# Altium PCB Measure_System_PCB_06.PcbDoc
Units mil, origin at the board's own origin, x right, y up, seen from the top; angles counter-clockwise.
Board outline 5905.51 x 3943.07 mil, 2 copper layers (Top Layer, Bottom Layer); 44 components, 29 nets, 115 pads, 0 vias.
Unrouted connection lines stored in the file: 73.
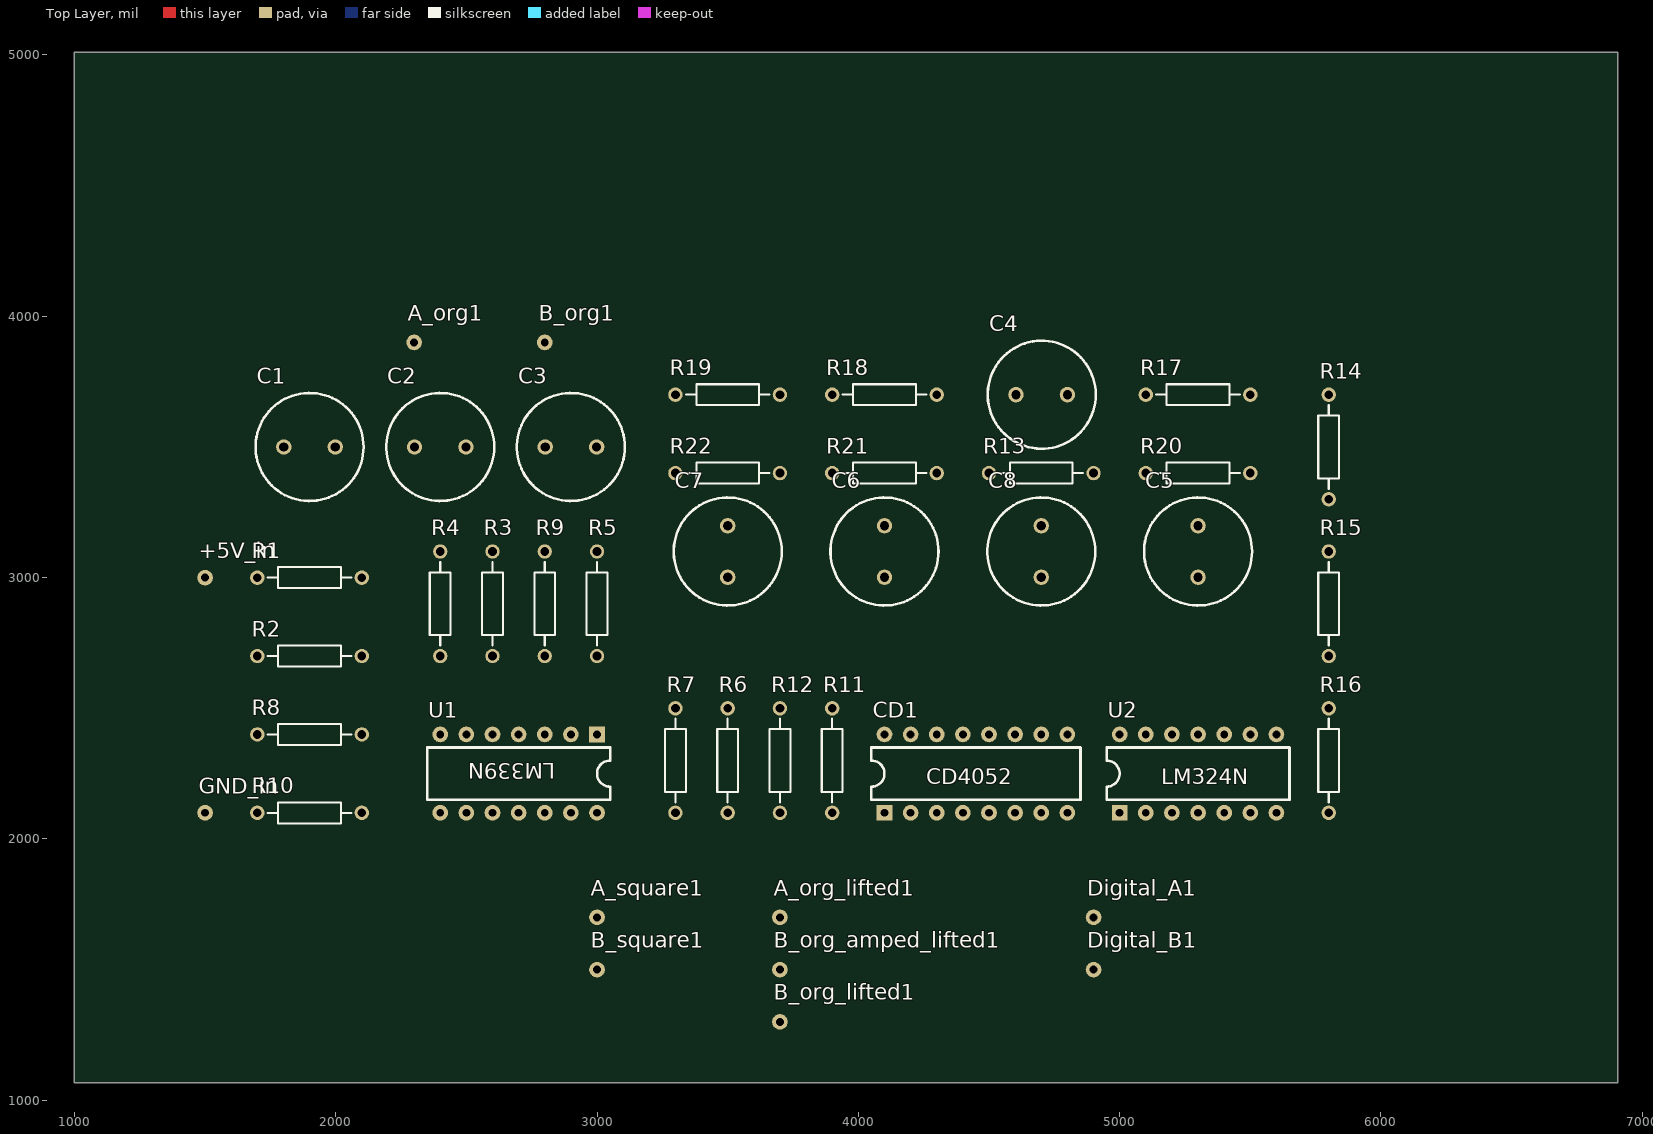
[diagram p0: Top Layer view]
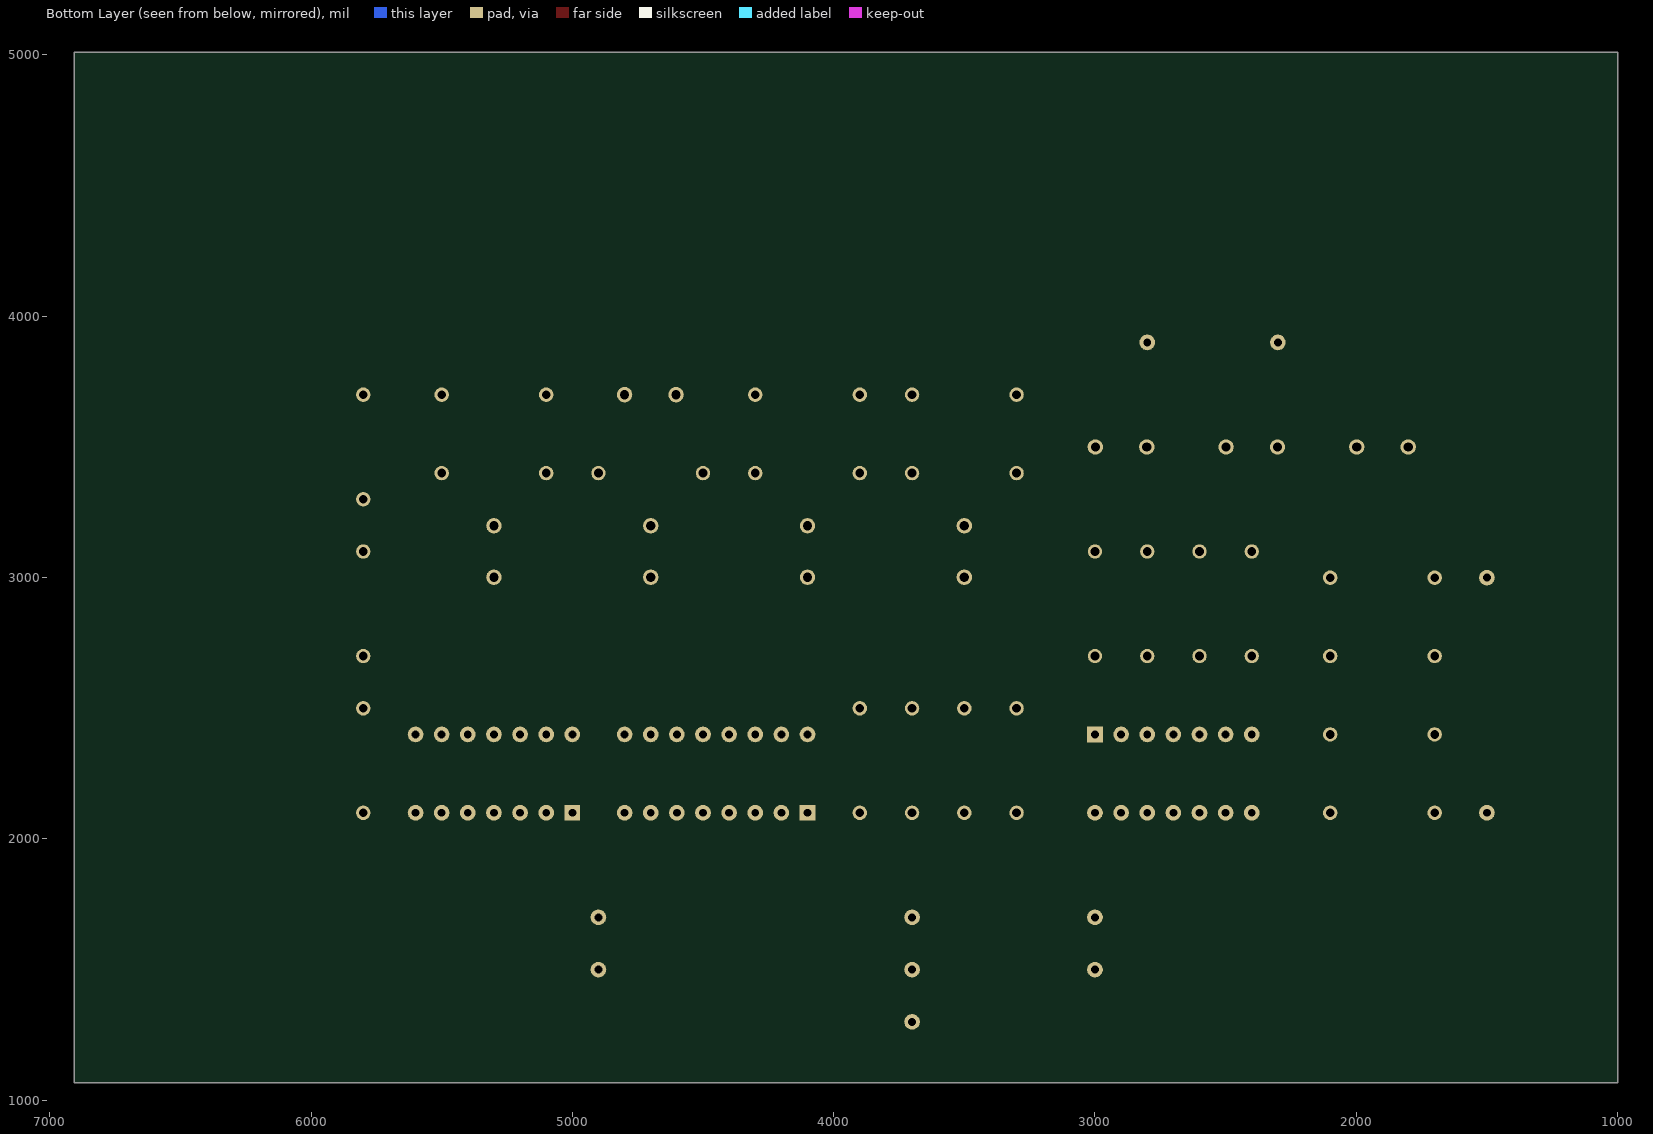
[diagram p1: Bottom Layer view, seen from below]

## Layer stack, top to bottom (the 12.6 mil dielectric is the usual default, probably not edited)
Top Solder: solder mask 0.4, Solder Resist, Dk 3.5
Top Layer: signal copper 1.4
Dielectric 1: dielectric 12.6, FR-4, Dk 4.8
Bottom Layer: signal copper 1.4
Bottom Solder: solder mask 0.4, Solder Resist, Dk 3.5

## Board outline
1000,1066.93 1000,5010 6905.51,5010 6905.51,1066.93

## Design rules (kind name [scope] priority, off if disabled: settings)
Clearance [All] p1: gap=39.37 ignorepadtopadclearanceinfootprint=FALSE
PolygonConnect [All] p1: connectstyle=Relief reliefconductorwidth=10 reliefentries=4 polygonreliefangle="90 Angle" airgapwidth=10
RoutingLayers [All] p1: top layer_v5=FALSE bottom layer_v5=TRUE
RoutingVias [All] p1: holewidth=28 width=50 viastyle="Through Hole" minholewidth=28 minwidth=50 maxholewidth=28 maxwidth=50
SolderMaskExpansion [All] p1: expansion=4 istentingtop=FALSE
Width [All] p1: maxlimit=393.7 minlimit=19.68 preferedwidth=39.37 minimp=50.000000 maximp=50.000000 favimp=50.000000
29 further rules are at their usual default settings.

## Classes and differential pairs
component class Part_Square: C1 C2 R1 R2 R3 R4 R5 R6 R7 R8 R9 R10 U1
component class Part_PGA: C3 C4 C5 C6 C7 C8 CD1 R11 R12 R13 R14 R15 R16 R17 R18 R19 R20 R21 R22 U2
component class Measure_System_Main: +5V_in A_org1 A_org_lifted1 A_square1 B_org1 B_org_amped_lifted1 B_org_lifted1 B_square1 Digital_A1 Digital_B1 GND_in

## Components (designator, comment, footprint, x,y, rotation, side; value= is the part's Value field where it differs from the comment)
+5V_in "Hole" Hole 1500,3000 r90 top
A_org1 "Hole" Hole 2300,3900 r90 top
A_org_lifted1 "Hole" Hole 3700,1700 r90 top
A_square1 "Hole" Hole 3000,1700 r90 top
B_org1 "Hole" Hole 2800,3900 r90 top
B_org_amped_lifted1 "Hole" Hole 3700,1500 r90 top
B_org_lifted1 "Hole" Hole 3700,1300 r0 top
B_square1 "Hole" Hole 3000,1500 r90 top
C1 "Cap Pol1" RB5-10.5 1900,3500 r180 top value=10u
C2 "Cap Pol1" RB5-10.5 2400,3500 r0 top value=10u
C3 "Cap Pol1" RB5-10.5 2900,3500 r0 top value=10u
C4 "Cap Pol1" RB5-10.5 4701.57,3700 r180 top value=10u
C5 "Cap Pol1" RB5-10.5 5300,3100 r270 top value=10u
C6 "Cap Pol1" RB5-10.5 4100,3100 r270 top value=10u
C7 "Cap Pol1" RB5-10.5 3500,3100 r270 top value=10u
C8 "Cap Pol1" RB5-10.5 4700,3100 r90 top value=10u
CD1 "CD4052" CD4052 4100,2100 r90 top
Digital_A1 "Hole" Hole 4900,1700 r90 top
Digital_B1 "Hole" Hole 4900,1500 r90 top
GND_in "Hole" Hole 1500,2100 r90 top
R1 "Res2" AXIAL-0.4 1900,3000 r180 top value=100k
R2 "Res2" AXIAL-0.4 1900,2700 r0 top value=100k
R3 "Res2" AXIAL-0.4 2600,2900 r90 top value=1k
R4 "Res2" AXIAL-0.4 2400,2900 r90 top value=1k
R5 "Res2" AXIAL-0.4 3000,2900 r90 top value=100k
R6 "Res2" AXIAL-0.4 3500,2300 r90 top value=100k
R7 "Res2" AXIAL-0.4 3300,2300 r90 top value=10k
R8 "Res2" AXIAL-0.4 1900,2400 r180 top value=10k
R9 "Res2" AXIAL-0.4 2800,2900 r270 top value=10k
R10 "Res2" AXIAL-0.4 1900,2100 r180 top value=10k
R11 "Res2" AXIAL-0.4 3900,2300 r270 top value=200
R12 "Res2" AXIAL-0.4 3700,2300 r270 top value=100k
R13 "Res2" AXIAL-0.4 4700,3400 r180 top value=100k
R14 "Res2" AXIAL-0.4 5800,3500 r90 top value=100k
R15 "Res2" AXIAL-0.4 5800,2900 r90 top value=100k
R16 "Res2" AXIAL-0.4 5800,2300 r90 top value=100k
R17 "Res2" AXIAL-0.4 5300,3700 r180 top value=50k
R18 "Res2" AXIAL-0.4 4100,3700 r180 top value=24k
R19 "Res2" AXIAL-0.4 3500,3700 r180 top value=12k
R20 "Res2" AXIAL-0.4 5300,3400 r0 top value=100k
R21 "Res2" AXIAL-0.4 4100,3400 r180 top value=100k
R22 "Res2" AXIAL-0.4 3500,3400 r180 top value=100k
U1 "LM339N" LM339N 3000,2400 r270 top
U2 "LM324N" LM324N 5000,2100 r90 top

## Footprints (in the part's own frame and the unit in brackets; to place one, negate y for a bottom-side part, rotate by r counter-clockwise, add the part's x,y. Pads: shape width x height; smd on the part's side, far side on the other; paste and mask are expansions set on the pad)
AXIAL-0.4 [mm] "Axial Device, Thru-Hole; 2 Leads; 0.4 in Pin Spacing"
  round 1.4 hole 0.85: 1(-5.08,0) 2(5.08,0)
  silkscreen extent -4.06,-1.02 4.06,1.02
CD4052 [mil]
  rect 60x60 hole 30: 1(0,0)
  round 60 hole 30 mask+4: 2(0,-100) 3(0,-200) 4(0,-300) 5(0,-400) 6(0,-500) 7(0,-600) 8(0,-700) 9(300,-700) 10(300,-600) 11(300,-500) 12(300,-400) 13(300,-300) 14(300,-200) 15(300,-100) 16(300,0)
  silkscreen extent 50,-750 250,50
Hole [mil]
  round 60 hole 30 mask+4: 1(0,0)
LM324N [mil]
  rect 60x60 hole 30: 1(0,0)
  round 60 hole 30 mask+4: 2(0,-100) 3(0,-200) 4(0,-300) 5(0,-400) 6(0,-500) 7(0,-600) 8(300,-600) 9(300,-500) 10(300,-400) 11(300,-300) 12(300,-200) 13(300,-100) 14(300,0)
  silkscreen extent 50,-650 250,50
LM339N [mil]
  rect 60x60 hole 30: 1(0,0)
  round 60 hole 30 mask+4: 2(0,-100) 3(0,-200) 4(0,-300) 5(0,-400) 6(0,-500) 7(0,-600) 8(300,-600) 9(300,-500) 10(300,-400) 11(300,-300) 12(300,-200) 13(300,-100) 14(300,0)
  silkscreen extent 50,-650 250,50
RB5-10.5 [mm] "Capacitor (Radial); 2 Leads"
  round 1.5 hole 0.9: 1(-2.5,0) 2(2.5,0)
  silkscreen extent -5.25,-5.25 5.25,5.25

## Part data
C1 C2 C3 C4 C5 C6 C7 C8: "Polarized Capacitor (Radial)"
R1 R2 R3 R4 R5 R6 R7 R8 R9 R10 R11 R12 R13 R14 R15 R16 R17 R18 R19 R20 R21 R22: "Resistor"

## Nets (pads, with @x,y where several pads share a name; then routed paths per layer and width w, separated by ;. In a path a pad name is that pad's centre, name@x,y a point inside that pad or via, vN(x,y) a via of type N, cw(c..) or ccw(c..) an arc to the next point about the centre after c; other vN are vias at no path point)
+5: +5V_in.1 R1.2 R5.2 R9.1 R10.2 R11.2 R12.2 R16.1 U1.3 U2.4
B_org: B_org1.1 C1.1 C3.1 R4.2
B_org_amp_1: C3.2 CD1.1 CD1.11 R14.2 U2.3 U2.5 U2.10
B_org_amp_2.5: C5.2 CD1.12
B_org_amp_5: C6.2 CD1.14
B_org_amp_10: C7.2 CD1.15
B_org_amped: C8.1 CD1.13
Digital_A: CD1.10 Digital_A1.1
Digital_B: CD1.9 Digital_B1.1
GND: C4.1 CD1.6 CD1.7 CD1.8 GND_in.1 R2.1 R6.1 R7.1 R8.2 R13.1 R15.1 U1.12 U2.11
NetA_org1_1: A_org1.1 C2.1 R3.2
NetA_org_lifted1_1: A_org_lifted1.1 C2.2 R5.1 R6.2
NetA_square1_1: A_square1.1 R9.2 U1.2
NetB_org_amped_lifted1_1: B_org_amped_lifted1.1 C8.2 R12.1 R13.2
NetB_org_lifted1_1: B_org_lifted1.1 C1.2 R1.1 R2.2
NetB_square1_1: B_square1.1 R10.1 U1.1
NetC4_2: C4.2 R17.1 R18.1 R19.1
NetC5_1: C5.1 R20.2 U2.8
NetC6_1: C6.1 R21.2 U2.7
NetC7_1: C7.1 R22.2 U2.1
NetCD1_16: CD1.16 R11.1
NetR3_1: R3.1 U1.5
NetR4_1: R4.1 U1.7
NetR7_2: R7.2 U1.4
NetR8_1: R8.1 U1.6
NetR14_1: R14.1 R15.2 R16.2
NetR17_2: R17.2 R20.1 U2.9
NetR18_2: R18.2 R21.1 U2.6
NetR19_2: R19.2 R22.1 U2.2
pads on no net: CD1.2 CD1.3 CD1.4 CD1.5 U1.8 U1.9 U1.10 U1.11 U1.13 U1.14 U2.12 U2.13 U2.14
